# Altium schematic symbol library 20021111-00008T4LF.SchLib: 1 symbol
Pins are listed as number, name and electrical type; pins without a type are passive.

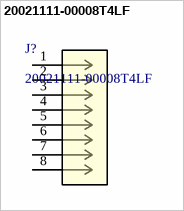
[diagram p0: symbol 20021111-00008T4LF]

## 20021111-00008T4LF
designator J?
No Description Available; Manufacturer_Name: Amphenol ICC
footprint CONN_20021111-00008T4LF_AMP
pins: 1, 2, 3, 4, 5, 6, 7, 8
